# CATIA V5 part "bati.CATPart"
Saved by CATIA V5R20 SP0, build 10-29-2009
Part number: bati
Bounding box of the stored display mesh (mm): x 0 to 48, y -63.471 to 76.982, z -50 to 90
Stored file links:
  E:\IAO_2010\iao\IAO_MMS_Groupe1\Problemes\tlampure\tlampure\tlampure\bati.CATPart
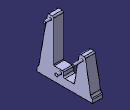
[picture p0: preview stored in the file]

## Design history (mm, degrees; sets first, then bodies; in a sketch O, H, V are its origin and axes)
Body1 (main body)
  Sketch1 on yz-plane, origin (0, 0, 0), H (0, 1, 0), V (0, 0, 1)
    line L1 (-63.0176, -50) -> (76.9824, -50)
    line L2 (-63.0176, -50) -> (-63.0176, -42)
    point P3 (-63.0176, -42)
    line L3 (-63.0176, -42) -> (-63.4712, -42.4536)
    point P4 (-58.7751, -37.7572)
    point P5 (-36.0201, 90)
    line L4 (-33.0885, 90) -> (-24.5201, 90)
    point P6 (-21.0201, 90)
    line L5 (31.7601, -27.9839) -> (42.8664, 37.6353)
    point P7 (43.5338, 41.5785)
    line L6 (47.5331, 41.5785) -> (55.7378, 41.5785)
    point P8 (58.5533, 41.5785)
    line L7 (59.0422, 38.8058) -> (71.9012, -34.1213)
    point P9 (72.4764, -37.3833)
    line L8 (74.964, -39.5705) -> (76.9824, -41.3452)
    point P10 (76.9824, -41.3452)
    line L9 (76.9824, -41.3452) -> (76.9824, -50)
    line L10 (7.4136, -30.5152) -> (28.7644, -30.5152)
    line L11 (-57.6105, -31.2186) -> (-36.5342, 87.1137)
    arc A1 centre (55.7378, 38.2232) radius 3.3554 from (59.0422, 38.8058) to (55.7378, 41.5785) ccw
    arc A2 centre (47.5331, 36.8454) radius 4.7331 from (42.8664, 37.6353) to (47.5331, 41.5785) cw
    arc A3 centre (81.1962, -32.4823) radius 9.4384 from (74.964, -39.5705) to (71.9012, -34.1213) cw
    arc A4 centre (28.7644, -27.4769) radius 3.0383 from (28.7644, -30.5152) to (31.7601, -27.9839) ccw
    arc A5 centre (7.4136, -26.8522) radius 3.663 from (7.4136, -30.5152) to (3.7507, -26.8761) cw
    arc A6 centre (-24.5201, 86.5) radius 3.5 from (-21.0201, 86.5) to (-24.5201, 90) ccw
    arc A7 centre (-33.0885, 86.5) radius 3.5 from (-36.5342, 87.1137) to (-33.0885, 90) cw
    arc A8 centre (-78.412, -27.5137) radius 21.1289 from (-63.4712, -42.4536) to (-57.6105, -31.2186) ccw
    line L12 (-21.0201, 86.5) -> (-21.0201, -14.6222)
    line L13 (-19.4726, -16.1698) -> (1.1917, -16.1698)
    line L14 (3.7506, -18.7287) -> (3.7507, -26.8761)
    arc A9 centre (1.1917, -18.7287) radius 2.5589 from (1.1917, -16.1698) to (3.7506, -18.7287) cw
    arc A10 centre (-19.4726, -14.6222) radius 1.5476 from (-21.0201, -14.6222) to (-19.4726, -16.1698) ccw
    length L1 = 140
    length L2 = 8
    distance L1 L4 = 140
    angle L1 L7 = 80
    angle L1 L8 = 41.323
    radius A1 = 3.3554
    radius A2 = 4.7331
    distance P9 P10 = 6
    radius A3 = 9.4384
    radius A4 = 3.0383
    distance P5 P6 = 15
    radius A6 = 3.5
    radius A7 = 3.5
    distance P3 P4 = 6
    radius A8 = 21.1289
    radius A9 = 2.5589
    radius A10 = 1.5476
    horizontal: L1 H, L4 H, L6 H, L10 H, L13 H
    vertical: L2 V, L9 V
    coincidence: L7 P8, L6 P8, L5 P7, L6 P7, L8 P9, L7 P9, L4 P6, L11 P5, L4 P5, L3 P4, L11 P4
    tangency: A1 L7, A1 L6, A2 L5, A2 L6, A3 L8, A3 L7, A4 L10, A4 L5, A5 L10, A6 L4, A7 L11, A7 L4, A8 L3, A8 L11, L12 A6, A9 L13, A9 L14, A10 L12, A10 L13
  Pad1: profile Sketch1, direction (1, 0, 0), length 25
  Sketch2 on end face of Pad1, origin (25, 0, 0), H (0, 1, 0), V (0, 0, 1)
    circle A1 centre (51.0883, 31.145) radius 3
  Pad2: profile Sketch2, direction (1, 0, 0), length 23
  Sketch3 on end face of Pad1, origin (25, 0, 0), H (0, 1, 0), V (0, 0, 1)
    circle A1 centre (-28.9472, 81.268) radius 3
  Pad3: profile Sketch3, direction (1, 0, 0), length 15
  Sketch4 on end face of Pad1, origin (25, 0, 0), H (0, 1, 0), V (0, 0, 1)
    circle A1 centre (-4.6044, -23.9715) radius 4
  Pad4: profile Sketch4, direction (1, 0, 0), length 9
  Sketch5 on end face of Pad1, origin (25, 0, 0), H (0, 1, 0), V (0, 0, 1)
  Point1: type Center, Curve edge [face of Pad3 from Sketch3.A1 | end face of Pad3]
